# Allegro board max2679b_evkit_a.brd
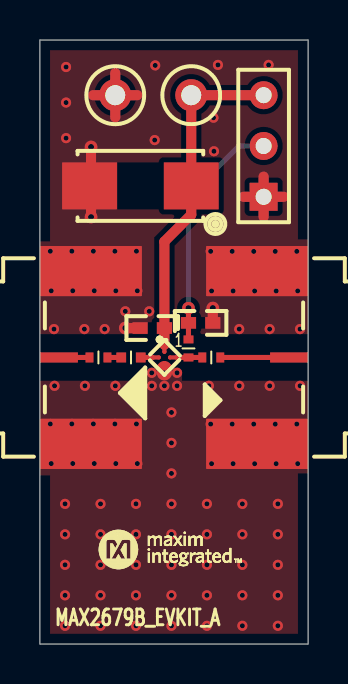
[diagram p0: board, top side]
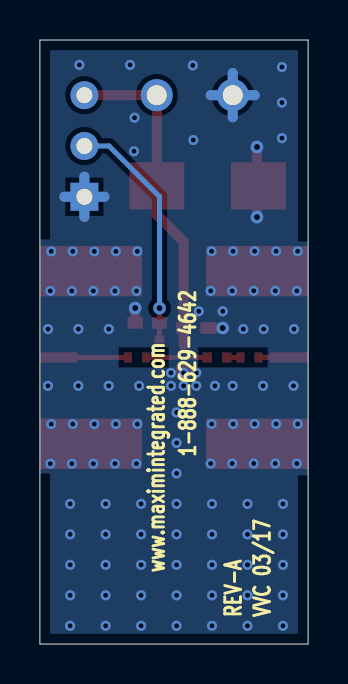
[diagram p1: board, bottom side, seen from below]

Outline 13.45 x 30.2 mm; copper layers: TOP, L2_GND, L3_GND, BOTTOM. Coordinates in mm from the lower left corner of the outline.
Outline path: 0,30.2 0,0 13.45,0 13.45,30.2 0,30.2

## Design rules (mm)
constraint set DEFAULT: min track width 0.508
net group 50OHMS: nets RFIN RFOUT UNNAMED_1_142-0701-851_I11_1 UNNAMED_1_142-0701-851_I51_1 UNNAMED_1_CAPNP_I7_1
nets with their own width: min track width 0.254; nets UNNAMED_1_CAPNP_I6_1

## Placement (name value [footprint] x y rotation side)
C2  0.1UF  [0402#2]  2.94 14.33 180 top
C3  10UF  [CAPMP6032X280M]  5.04 22.91 180 top
C5  1000PF  [0402]  5.63 15.8 0 top
C8  0.1UF  [0402#2]  8.59 14.33 0 top
C9  1000PF  [0402]  8.06 16.06 0 top
EV_KIT_BOX1  SMALL BOX  [EVKIT_PACKAGING]  -32.27 43.79 0 top
GND  N/A  [TP_180P120D460H]  3.78 27.44 0 top
L1  13NH  [0402#2]  4.57 14.33 0 top
NOREF  -  []  0 0 90 top
NOREF#2  -  []  0 30.2 0 top
NOREF#3  -  []  12.7 -28.55 0 top
NOREF#4  -  []  6.44 81 0 top
NOREF#5  -  []  3.93 4.72 0 top
R1  24.9K  [0402#2]  7.45 14.78 90 top
RFIN  142-0701-851  [JOHNSON_142-0701-851]  -5.55 14.33 270 top
RFOUT  142-0701-851  [JOHNSON_142-0701-851]  19 14.33 90 top
SHDNB  HEADER_3P  [HDR_3P]  11.22 22.36 90 top
U1  MAX2679BENS+  [BGA4C40P2X2_82X82X50M]  6.24 14.33 315 top
VCC  N/A  [TP_180P120D460H]  7.59 27.44 0 top

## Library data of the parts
C2 C8 = CAP_NP: alternate symbols: 0402_NOSILK,CAPC1005X50L,CAP0402-NOT_FOR_TEST; part number: CAP_NP_0402CAP-0402,0.1UF,20-000U1-04A
C3 = CAP_POL: part number: CAP_POL_6032CAP-CAPMP6032X280M,10UF,20-0010U-D6
C5 C9 = CAP_NP: alternate symbols: (0402_NOSILK); part number: CAP_NP_0402CAP-0402,1000PF,20-1000P-05
EV_KIT_BOX1 = EV_KIT_BOX: part number: EV_KIT_BOX_ACCESSORY-N/A,SMALL BOX,EVKIT_PACKAGING
GND = TP: part number: TP_TP-TP_180P120D460H,N/A,02-TPMINI5001-00
L1 = INDUCT: alternate symbols: 0402_NOSILK,INDC1005X55L; part number: INDUCT_0402-0402,13NH,50-0013N-0PM
R1 = RES: alternate symbols: (0402_NOSILK,RESC1005X50L); part number: RES_0402RES-0402,24.9K,80-024K9-23
RFIN RFOUT = 142-0701-851: alternate symbols: JOHNSON_142-0701-851_ALT_PIN1_20MILS;JOHNSON_142-0701-851_ALT_PIN1_12MILS; part number: 142-0701-851_TMD-JOHNSON_142-0701-851,142-0701-851,01-14207018512P-01
SHDNB = HEADER_3P: part number: HEADER_3P_SIP-HDR_3P,HEADER_3P,01-80010003100010003P-21
U1 = EK_MAX2679: alternate symbols: BGA4C40P2X2_82X82X50L; part number: EK_MAX2679_WLP4-BGA4C40P2X2_82X82X50M,MAX2679BENS+,N/A
VCC = TP: part number: TP_TP-TP_180P120D460H,N/A,02-TPMINI5000-00

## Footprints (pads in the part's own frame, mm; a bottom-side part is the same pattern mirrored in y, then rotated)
0402
  rect 0.762x0.584 smd: 1(-0.61,0) 2(0.61,0)
0402#2
  rect 0.4x0.5 smd: 1(-0.45,0) 2(0.45,0)
BGA4C40P2X2_82X82X50M
  round 0.21 smd: A1(-0.2,0.2) A2(0.2,0.2) B1(-0.2,-0.2) B2(0.2,-0.2)
CAPMP6032X280M
  rect 2.75x2.35 smd: 1(-2.55,0) 2(2.55,0)
HDR_3P
  rect 1.4x1.4 hole 0.8: 1(0,0)
  round 1.4 hole 0.8: 2(2.54,0) 3(5.08,0)
JOHNSON_142-0701-851
  rect 0.508x1.905 smd: 1(0,6.502)
  rect 2.5x5.1 smd: 2(4.318,8.1) 3(-4.318,8.1) 4(-4.318,8.1) 5(4.318,8.1)
TP_180P120D460H
  round 1.6 hole 1: 1(0,0)

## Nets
GND: C3.2(B) C5.1 C9.2 GND.1(TP1) RFIN.2 RFIN.3 RFIN.4 RFIN.5 RFOUT.2 RFOUT.3 RFOUT.4 RFOUT.5 SHDNB.1 U1.B2
VCC: C3.1 C5.2 SHDNB.3 U1.A1 VCC.1(TP1)
RFIN: L1.2 U1.B1
RFOUT: C8.1 R1.1 U1.A2
UNNAMED_1_142-0701-851_I11_1: C2.2 RFIN.1
UNNAMED_1_142-0701-851_I51_1: C8.2 RFOUT.1
UNNAMED_1_CAPNP_I6_1: C9.1 R1.2 SHDNB.2
UNNAMED_1_CAPNP_I7_1: C2.1 L1.1

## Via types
v1: diameter 0.635, hole 0.305, TOP to BOTTOM, 5 vias
v2: diameter 0.508, hole 0.254, TOP to BOTTOM, 109 vias

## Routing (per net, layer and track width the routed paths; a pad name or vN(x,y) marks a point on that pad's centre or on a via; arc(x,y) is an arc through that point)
GND: length 39.2
  TOP w0.203: U1.B2 6.24,13.77
  TOP w0.508: 11.22,21.36 SHDNB.1 ; SHDNB.1 12.22,22.36 ; SHDNB.1 10.21,22.36 ; SHDNB.1 11.22,23.37 ; 3.78,26.34 GND.1 ; GND.1 2.67,27.44 ; GND.1 3.78,28.55 ; GND.1 4.88,27.44 ; v1(4.28,15.8) 4.28,15.8 C5.1 ; C9.2 8.67,16.79 v1(8.67,16.8) ; v1(2.56,21.35) v1(2.56,24.85)
  TOP w0.762: 6.24,13.77 v2(6.24,13.56)
  L2_GND w0.508: 11.22,21.36 SHDNB.1 ; SHDNB.1 11.22,23.37 ; SHDNB.1 12.22,22.36 ; SHDNB.1 10.21,22.36 ; 3.78,26.34 GND.1 ; GND.1 4.88,27.44 ; GND.1 3.78,28.55 ; GND.1 2.67,27.44
  L3_GND w0.508: 10.21,22.36 SHDNB.1 ; SHDNB.1 11.22,21.36 ; SHDNB.1 12.22,22.36 ; SHDNB.1 11.22,23.37 ; GND.1 4.88,27.44 ; GND.1 2.67,27.44 ; GND.1 3.78,26.34 ; GND.1 3.78,28.55
  BOTTOM w0.508: SHDNB.1 11.22,23.37 ; SHDNB.1 10.21,22.36 ; SHDNB.1 11.22,21.36 ; SHDNB.1 12.22,22.36 ; 2.67,27.44 GND.1 ; GND.1 4.88,27.44 ; GND.1 3.78,28.55 ; GND.1 3.78,26.34
  vias: v2(0.52,19.64) v2(0.57,17.66) v2(0.52,11) v2(0.57,9.02) v2(0.71,15.75) v2(0.73,12.91) v2(1.26,7.01) v2(1.26,5.48) v2(1.26,3.96) v2(1.26,2.43) v2(1.26,0.91) v2(1.31,28.85) v2(1.31,27.07) v2(1.31,25.29) v2(1.6,19.64) v2(1.65,17.66) v2(1.6,11) v2(1.65,9.02) v2(2.23,15.75) v2(2.26,12.91) v2(2.68,19.64) v2(2.68,11) v2(2.73,17.66) v2(2.73,9.02) v2(3.04,7.01) v2(3.04,5.48) v2(3.04,3.96) v2(3.04,2.43) v2(3.04,0.91) v2(3.25,15.75) v2(3.76,19.64) v2(3.78,12.91) v2(3.76,11) v2(3.81,17.66) v2(3.81,9.02) v2(4.28,16.64) v2(4.67,12.91) v2(4.84,19.64) v2(4.89,17.66) v2(4.84,11) v2(4.89,9.02) v2(4.82,7.01) v2(4.82,5.48) v2(4.82,3.96) v2(4.82,2.43) v2(4.82,0.91) v2(5.48,16.64) v2(5.61,13.56) v2(5.61,12.91) v2(5.78,28.93) v2(5.76,25.2) v2(6.24,12.91) v2(6.6,11.58) v2(6.6,10.05) v2(6.6,8.53) v2(6.6,7.01) v2(6.6,5.48) v2(6.6,3.96) v2(6.6,2.43) v2(6.6,0.91) v2(6.88,13.56) v2(6.88,12.91) v2(8.37,7.01) v2(8.37,5.48) v2(8.37,3.96) v2(8.37,2.43) v2(8.37,0.91) v2(8.47,12.91) v2(8.56,19.63) v2(8.56,11) v2(8.61,17.65) v2(8.61,9.02) v2(8.7,26.31) v2(8.73,24.64) v2(8.93,28.95) v2(9.64,19.63) v2(9.69,17.65) v2(9.64,11) v2(9.69,9.02) v2(9.99,15.75) v2(10,12.91) v2(10.15,7.01) v2(10.15,5.48) v2(10.15,3.96) v2(10.15,2.43) v2(10.15,0.91) v2(10.72,19.63) v2(10.77,17.65) v2(10.72,10.99) v2(10.77,9.01) v2(11.47,28.95) v2(11.52,15.75) v2(11.52,12.91) v2(11.8,19.63) v2(11.84,17.65) v2(11.8,10.99) v2(11.84,9.01) v2(11.93,7.01) v2(11.93,5.48) v2(11.93,3.96) v2(11.93,2.43) v2(11.93,0.91) v2(12.88,19.63) v2(12.88,11) v2(12.92,17.65) v2(12.92,9.02) v2(13.04,15.75) v2(13.04,12.91)
VCC: length 17
  TOP w0.203: U1.A1 6.24,14.96
  TOP w0.508: SHDNB.3 VCC.1 C3.1 7.59,21.47 6.24,20.12 C5.2 6.24,14.96
RFIN: length 0.9
  TOP w0.203: U1.B1 5.65,14.33
  TOP w0.254: 5.65,14.33 L1.2
RFOUT: length 1.6
  TOP w0.203: U1.A2 6.87,14.33
  TOP w0.254: 6.87,14.33 R1.1 C8.1
UNNAMED_1_142-0701-851_I11_1: length 1.5
  TOP w0.254: C2.2 RFIN.1
UNNAMED_1_142-0701-851_I51_1: length 3.5
  TOP w0.254: RFOUT.1 C8.2
UNNAMED_1_CAPNP_I6_1: length 12
  TOP w0.254: R1.2 C9.1 v1(7.45,16.79)
  BOTTOM w0.254: SHDNB.2 9.98,24.9 7.45,22.37 v1(7.45,16.79)
UNNAMED_1_CAPNP_I7_1: length 0.7
  TOP w0.254: L1.1 C2.1

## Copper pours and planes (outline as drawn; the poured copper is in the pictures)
GND on TOP: 0.51,0.51 0.51,8.43 0,8.43 0,13.16 5.35,13.16 5.35,13.67 5.5,13.82 5.76,13.82 5.96,14.02 5.96,15.19 5.76,15.39 5.35,15.39 5.35,15.49 4.67,15.49 4.67,15.49 0,15.49 0,20.13 0.51,20.13 0.51,29.69 12.94,29.69 12.94,20.23 13.44,20.23 13.44,15.49 7.13,15.49 7.13,15.39 6.59,15.39 6.47,15.27 6.47,14.07 6.72,13.82 6.97,13.82 7.13,13.67 7.13,13.16 13.44,13.16 13.44,8.53 12.94,8.53 12.94,0.51
GND on BOTTOM, L2_GND, L3_GND: 0.51,0.51 0.51,8.43 0,8.43 0,20.13 0.51,20.13 0.51,29.69 12.94,29.69 12.94,20.23 13.44,20.23 13.44,8.53 12.94,8.53 12.94,0.51

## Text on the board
Ref Des/Silkscreen Bottom: VVC 03/17 | REV-A | 1-888-629-4642 | www.maximintegrated.com
Ref Des/Silkscreen Top: 1 | MAX2679B_EVKIT_A
DIMENSION: Allow all instances of copper to edge of board per fab data
User.9: NOTES: | FINISH: | TESTING: | MISCELLANEOUS: | TOOLING: | 16.  VENDOR LOGO & DATE CODE REQUIRED IN INK ON BOTTOM SIDE ONLY. DATE CODE FORMAT MUST BE YYWW ONLY | 17.  FINAL ELECTRICAL TEST TO BE PERFORMED USING PROVIDED IPC-D-356A NETLIST OR ODB++ FORMAT FILE. | 18.  A TIME DOMAIN REFLECTOMETER REPORT FOR EACH IMPEDANCE CONTROLLED LAYER AND A CERTIFICATE | 15.  CHECK ALL THAT APPLY | 14.  CHECK ALL THAT APPLY | 19.  IF PRESENT, ALL BLIND/BURIED VIAS WITH AN ASPECT RATIO <1:1 TO BE PLATED SHUT WITH COPPER WHEN | 21.  FINISHED SURFACE CONTACTS AND FILLED VIAS TO BE FREE OF ANY PITS. SCRATCHES PROBE MARKS | 23.  PEMNUT | 20.  FOR ALL DRILL INFORMATION REFER TO DRILL CHART. | 13.  DRILL SIZES ARE FINISHED HOLE SIZES. ALL HOLES SHALL BE LOCATED WITHIN .005 DTP. | 22.  THIEVING: | 9.  ALL TRACES FILLETED OPTION TO ENHANCE RELIABILITY AT PAD JUNCTIONS | 10.  LAYER TO LAYER REGISTRATIONS SHALL BE WITHIN .003 INCHES. | MATERIAL: | 11.  PLATING SPECIFICATION: | 12.  CHECK ALL THAT APPLY | 8.  IF STATED IN THE LAMINATION DIAGRAM, THE DIELECTRIC THICKNESS OF ANY | 1.  DIMENSIONS ARE IN INCHES (EXCEPT WHERE NOTED). | 3.  THE PCB SHALL BE FABRICATED TO IPC-6012, TYPE X, CLASS 2. | 4.  BOARD MATERIAL & CONSTRUCTION SHALL MEET THE REQUIREMENTS OF UL796 | 5.  OVERALL BOARD THICKNESS REFER TO LAMINATION DIAGRAM. TOLERANCE APPLIES | 6.  BOW & TWIST NOT TO EXCEED 0.0075 IN. (0.75%) PER LINEAR INCH. | 7.  PHOTO ETCH CIRCUITRY PER ENCLOSED GERBER RS274X OR ODB++ FORMAT FILE. | 2.  BOARD MATERIAL: | ( )  FINISH CONDUCTOR SURFACES: IMMERSION GOLD, 2-5 MICRO INCHES OVER | (X)  STARTING COPPER WEIGHT FOR OUTER LAYERS TO BE (1 OZ), THE FINISH COPPER WEIGHT IS (1 OZ). | ( )  STARTING COPPER WEIGHT FOR OUTER LAYERS TO BE (1 OZ), THE FINISH COPPER WEIGHT IS (2 OZ). | ( )  STARTING COPPER WEIGHT FOR OUTER LAYERS TO BE (2 OZ), THE FINISH COPPER WEIGHT IS (2 OZ)MINIMUM. | ( )  OTHER ________________________ | (X)  FINISH CONDUCTOR SURFACES: IMMERSION GOLD, 3-8 MICRO INCHES OVER | ( )  FINGERS TO BE GOLD PLATED. | (X)  GREEN SOLDERMASK OVER BARE COPPER/BARE GOLD (BOTH SIDES) WITH LIQUID PHOTO IMAGEABLE INK (LPI) | ( )  GREEN TAIYO PSR-4000 | ( )  ELECTRODEPOSITED HARD GOLD PLATE, TYPE 1 (99.7% MIN GOLD), GRADE C | ( )  LEAD FREE AND RoHS COMPLIANT OR EQUIVALENT LEAD FREE PLATING | (X)  APPLY SILKSCREEN USING A NON-CONDUCTIVE, WHITE EPOXY | THE STARTING WEIGHT CAN BE (0.5 OZ) AS LONG AS THE FINISH COPPER WEIGHT IS (2 OZ). | THE STARTING WEIGHT CAN BE (<2 OZ) AS LONG AS THE FINISH COPPER WEIGHT IS (2 OZ). | MINIMUM BARREL PLATING OF .001 IN. PLATED HOLES SHALL NOT BE ROUGH OR IRREGULAR | SO AS TO HINDER PROPER SOLDER WICKING. | USED AS VIA-IN PAD OR AS A STACKED VIA. BLIND/BURIED VIAS WITH AN ASPECT RATIO >1:1 TO BE FILLED | ( )  NON-CONDUCTIVE EPOXY. FILL AND CAP ALL 0.XXXX INCH DRILLED VIAS. | ( )  SILVER. FILL AND CAP ALL 0.XXXX INCH DRILLED VIAS. | (REQUIRED UNLESS OTHERWISE SPECIFIED IN QUOTE) | THE PCB SHALL HAVE A VERIFICATION STAMP. | WITH NON-CONDUCTIVE EPOXY. UNLESS OTHERWISE SPECIFIED. | OR OTHER DEFORMITIES THAT COULD EFFECT THE APPERANCE AND PERFORMACE OF THE CONTACT | SURFACE. CONTACTS ARE TO BE AS FLAT AS POSSIBLE. NOT TO EXCEED +/- 0.001" OF FLATNESS. | OF COMPLIANCE SHALL BE PROVIDED BY VENDOR AT TIME OF SHIPMENT. INSTANCES WHERE TDR TESTING | CAN'T BE PERFORMED BECAUSE THE TRACE LENGTH IS TOO SHORT ON THE OUTER LAYERS AT THE PIN ESCAPES | IS ACCEPTABLE, ALL OTHER INSTANCES MUST BE REPORTED. | ( )  SUPPLIER MAY ADD THIEVING TO COMPENSATE FOR LOW COPPER DENSITY AREAS ON THIS DESIGN. | WHERE SPACING PERMITS. | LEGEND TO LEGEND +/- 0.007 INCHES | (X)  SUPPLIER MAY NOT ADD THIEVING TO COMPENSATE FOR LOW COPPER DENSITY AREAS ON THIS DESIGN. | ( )  PEMNUTS TO BE INSTALLED BY SUPPLIER. | ( )  PEMNUTS NOT TO BE INSTALLED BY SUPPLIER. | (X)  NOT APPLICABLE | (X)  ISOLA 370HR OR EQUIVALENT | ( )  NELCO-4000-13 | ( )  MEGTRON 6 | ( )  ROGERS 4350B | ( )  ROGERS 4003C | ( )  ISOLA-FR408HR OR EQUIVALENT | CONTROLLED IMPEDANCE LAYER IS FOR REFERENCE ONLY. FINAL ACCEPTANCE | SHALL BE DETERMINED BY THESE LAYERS HAVING A CHARACTERISTIC | IMPEDANCE OF +/-10% OHMS AS STATED IN THE LAMINATION DIAGRAM. THE | VENDOR CAN MAKE ADJUSTMENTS AS LONG AS THE STATED IMPEDANCE AND | OVERALL BOARD THICKNESS IS MAINTAINED. ANY ADJUSTMENT MADE TO TRACE | WIDTH OR SPACING MUST HAVE PRIOR WRITTEN APPROVAL FROM MAXIM. | ( )  FILLETED | (X)  NOT FILLETED | WORKMANSHIP SHALL CONFORM TO IPC-A-600, CLASS 2, CURRENT REVISIONS. | WITH FLAMMABILITY RATING OF 94V-O. | AFTER ALL LAMINATION AND PLATING PROCESSES. IT IS TO BE MEASURED FROM | TOP PCB METAL TO BOTTOM PCB METAL UNLESS OTHERWISE SPECIFIED. | BOW & TWIST SHOULD BE MEASURED PER IPC-TM-650, METHOD 2.4.22. | DRILL LOCATION AND SIZE CONTROLLED BY EXCELLON CNC DRILL FILE. | FOR OUTER LAYERS WHERE SPACING PREVENTS THE USE OF (1 OZ) AS A STARTING WEIGHT, | FOR OUTER LAYERS WHERE SPACING PREVENTS THE USE OF (2 OZ) AS A STARTING WEIGHT, | UNLESS OTHERWISE SPECIFIED | FOR OUTER LAYERS WHERE SPACING PREVENTS THE USE OF (1 OZ) AS A STARTING WEIGHT | THE STARTING WEIGHT CAN BE (0.5 OZ) AS LONG AS THE FINISH COPPER WEIGHT IS (1 OZ) | 100 MICRO INCHES MINIMUM OF ELECTROLESS NICKEL. | (KNOOP HARDNESS 130-200), CLASS 1 (50-100 MICRO INCHES THICK) IN ACCORDANCE WITH MIL-G-45204C. | GENERAL SURFACING REQUIREMENTS MUST MEET ANSI/IPC-A-600(CURRENT REV) SECTION 4.0, | CLASS 3 (50-100 MICROINCHES THICK) OVER ELECTRODEPOSITED NICKEL PLATE | IN ACCORDANCE WITH ANSI/IPC-A-600D, SECTION 4.0, CLASS 3 (200-600 MICROINCHES THICK). | 118-236 MICRO INCHES MINIMUM OF ELECTROLESS NICKEL. | PER ARTWORK. | BASED INK PER ARTWORK. | (USE CHECKED ITEMS FOR MATERIAL) | (USE CHECKED ITEMS FOR PLATING) | (USE CHECKED ITEMS FOR TOOLING) | UNLESS OTHERWISE SPECIFIED: | NOT TO SCALE | TEMPLATE REV 2.1 | TOLERANCES UNLESS OTHERWISE SPECIFIED | +/- | FRACTIONS | SEE NOTES | .XXX +/- .005 | .XX +/- .01 | DECIMALS | ANGLES | THE INFORMATION CONTAINED IN THIS DOCUMENT | IS PROPRIETARY TO MAXIM. THE INFORMATION IN | THIS DOCUMENT IS NOT TO BE SHOWN, REPRODUCED, | OR DISCLOSED TO ANYONE OUTSIDE OF MAXIM | WITHOUT PRIOR WRITTEN PERMISSION FROM MAXIM. | DRAWN BY: | CHECKED BY: | APPR. BY: | V. CANAZARES | J. ALIM | R. RATILLA | DATE: | 01/17/2017 | 03/29/2017 | 03/28/2017 | SIZE | E | DRAWING NO. | SHEET 1 OF 1 | REV | A | DESCRIPTION | REVISIONS | APPROVED | DATE | TITLE: | P1 | P2 | RELEASE TO PROD | RELEASE | REMOVE CKT B | 09/02/16 | 03/28/17 | 02/29/16 | FABRICATION DWG. | MAX2679B_EVKIT_A
User.33: FIGURE | SIZE | 10.0 | 12.0 | 31.5 | 39.37 | TOLERANCE | +3.0/-8.0 | +3.0/-10.0 | +3.0/-3.0 | PLATED | ALL UNITS ARE IN MILS | QTY | 109 | 5 | 3 | 2 | NOTES | DRILL CHART: TOP to BOTTOM
